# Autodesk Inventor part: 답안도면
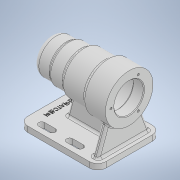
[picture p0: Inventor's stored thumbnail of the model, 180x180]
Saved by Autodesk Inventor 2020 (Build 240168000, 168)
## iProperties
Created: 2021-10
Part Number: 답안도면
Material: 일반
Document SubType Name: Modeling
Designer: user
Density: 1 g/cm^3
Appearance: 기본값
Author: user
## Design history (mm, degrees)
sketch "스케치1"
  geometry: L1 (0, 0)-(0, 34); L2 (0, 34)-(-32, 34); L3 (-32, 34)-(-32, 30); L4 (-32, 30)-(-66, 30); L5 (-66, 30)-(-66, 27); L6 (-66, 27)-(-88, 27); L7 (-88, 27)-(-88, 25); L8 (-88, 25)-(-112, 25); L9 (-112, 25)-(-112, 0); L10 (-112, 0)-(0, 0)
  constraints: 20 end point, 9 perpendicular, 1 vertical
  dimensions: "d0" = 24 distance of L7.end L8.end; "d1" = 46 distance between parallel lines of L5 L9; "d2" = 80 distance between parallel lines of L3 L9; "d3" = 112 distance between parallel lines of L1 L9; "d4" = 50 diameter of L8 L10; "d5" = 54 diameter of L6 L10; "d6" = 60 diameter of L4 L10; "d7" = 68 diameter of L2 L10
revolve "회전1" sketch "스케치1" stored, may be unused: angle "d8" = 90 deg
sketch "스케치2"
  geometry: C1 r 21 at (0, 0); 1 further point
  constraints: 1 centre point, 1 coincident
  dimensions: "d9" = 42 diameter of C1
extrude "돌출1" cut sketch "스케치2" distance "d10" = 15; taper "d11" = 0 deg
sketch "스케치3"
  geometry: C1 r 24 at (0, 0); 1 further point
  constraints: 1 centre point, 1 coincident
  dimensions: "d12" = 48 diameter of C1
extrude "돌출2" cut sketch "스케치3" distance "d13" = 54; taper "d14" = 0 deg
sketch "스케치4"
  geometry: C1 r 21 at (0, 0); 1 further point
  constraints: 1 centre point, 1 coincident
  dimensions: "d15" = 42 diameter of C1
extrude "돌출3" cut sketch "스케치4" distance "d16" = 12; taper "d17" = 0 deg
sketch "스케치5"
  geometry: C1 r 24 at (0, 0) reference; C2 r 17.5 at (0, 0); 1 further point
  constraints: 1 centre point, 1 coincident
  dimensions: "d18" = 35 diameter of C2
extrude "돌출4" cut sketch "스케치5" distance "d19" = 18; taper "d20" = 0 deg
sketch "스케치6"
  geometry: C1 r 16 at (0, 0); 1 further point
  constraints: 1 centre point, 1 coincident
  dimensions: "d21" = 32 diameter of C1
extrude "돌출5" cut sketch "스케치6" distance "d22" = 4; taper "d23" = 0 deg
sketch "스케치7"
  geometry: C1 r 21 at (0, 0) reference; C2 r 10.5 at (0, 0); 1 further point
  constraints: 1 centre point, 1 coincident
  dimensions: "d24" = 21 diameter of C2
extrude "돌출6" cut sketch "스케치7" distance "d25" = 3; taper "d26" = 0 deg
node "작업 평면1"
sketch "스케치10"
  geometry: L1 (112, 45)-(0, 45); L2 (0, 45)-(0, -45); L3 (0, -45)-(112, -45); L4 (112, -45)-(112, 45); L5 (112, 45)-(0, -45); L6 (0, 45)-(112, -45); L7 (112, 25)-(112, -25) reference; 3 further points
  constraints: 12 end point, 3 midpoint, 2 parallel, 1 horizontal, 1 horizontal alignment, 1 perpendicular, 1 point on line
  dimensions: "d28" = 112 distance of L3.end L2.end; "d29" = 90 distance of L2.end L1.end
extrude "돌출7" join sketch "스케치10" distance "d30" = 8; taper "d31" = 0 deg
sketch "스케치11"
  geometry: L1 (-85, -4)-(-8, -4); L2 (-8, -4)-(-8, 4); L3 (-8, 4)-(-85, 4); L4 (-85, 4)-(-85, -4); L5 (-85, -4)-(-8, 4); L6 (-8, -4)-(-85, 4); L7 (-112, -45)-(0, -45) reference; L8 (0, -45)-(0, 45) reference; 4 further points
  constraints: 12 end point, 4 midpoint, 2 parallel, 1 horizontal, 1 horizontal alignment, 1 perpendicular
  dimensions: "d34" = 8 distance between parallel lines of L8 L2; "d35" = 8 distance of L3.end L1.start; "d36" = 77 distance of L2.end L3.end
extrude "돌출8" join sketch "스케치11" stored distance "d37" = 8; taper "d38" = 0 deg
sketch "스케치12"
  geometry: L1 (-41, -8)-(-41, 0) reference; L2 (-41, 0)-(0, 0) reference; L3 (0, 0)-(0, 28.236) reference; L4 (8, 28.236)-(8, 0) reference; L5 (8, 0)-(49, 0) reference; L6 (49, 0)-(49, -8) reference; L7 (49, -8)-(-41, -8) reference; L8 (0, 0)-(8, 0) reference; L9 (-19.409, 37.342)-(-33, 0); L10 (49, 0)-(-41, 0) reference; C1 r 21 at (4, 62) reference; A1 r 34 centre (4, 62) between (8, 28.236) and (0, 28.236) reference; A2 r 34 centre (4, 62) between (0, 28.236) and (8, 28.236) reference; 2 further points
  constraints: 2 end point, 1 point on circle, 1 point on line
  dimensions: "d39" = 8 distance from line of L1 L9.end; "d40" = 110 deg angle of L2 L9
extrude "돌출9" join sketch "스케치12" distance "d41" = 8; taper "d42" = 0 deg
sketch "스케치14"
  geometry: L1 (-92, 33)-(-77, 33); L2 (-92, 28.5)-(-77, 28.5); L3 (-77, 37.5)-(-92, 37.5); L4 (-112, 45)-(-112, -45) reference; L5 (-52, 33)-(-37, 33); L6 (-52, 28.5)-(-37, 28.5); L7 (-37, 37.5)-(-52, 37.5); A1 r 4.5 centre (-92, 33) between (-92, 37.5) and (-92, 28.5); A2 r 4.5 centre (-77, 33) between (-77, 28.5) and (-77, 37.5); A3 r 4.5 centre (-52, 33) between (-52, 37.5) and (-52, 28.5); A4 r 4.5 centre (-37, 33) between (-37, 28.5) and (-37, 37.5); 3 further points
  constraints: 16 end point, 8 point on circle, 8 tangent, 4 centre point, 2 horizontal, 2 midpoint, 2 parallel
  dimensions: "d43" = 9 diameter of A2; "d44" = 20 distance from line of L1.start L4; "d45" = 15 distance of L1.end L1.start; "d46" = 9 diameter of A4; "d47" = 25 distance of L5.start L1.end; "d48" = 15 distance of L5.end L5.start; "d49" = 33 vertical distance of point (0, 0) point (-84.5, 33); "d50" = 33 vertical distance of point (0, 0) point (-44.5, 33)
extrude "돌출10" cut sketch "스케치14" distance "d51" = 30; taper "d52" = 0 deg
sketch "스케치16"
  geometry: C1 r 10.5 at (0, 0) reference; 2 further points
  constraints: 1 horizontal alignment
  dimensions: "d54" = 26 distance of point (0, 0) point (-26, 0)
hole "구멍1" sketch "스케치16" at (-26, 0) diameter "d55" = 3.242; stored, may be unused: countersink angle "d59" = 90 deg, drill point angle "d61" = 118 deg; dims "d56" = 8, "d57" = 4, "d58" = 2, "d60" = 11.8
chamfer "모따기1" distance "d65" = 1; stored, may be unused: second distance "d66" = 2, angle "d67" = 45 deg
fillet "모깎기1" dims "d68" = 3
fillet "모깎기2" dims "d69" = 0.3
fillet "모깎기3" dims "d70" = 3
fillet "모깎기4" dims "d71" = 8
fillet "모깎기5" dims "d72" = 3
feature "면 기울기1" dims angle "d73" = 15 deg
fillet "모깎기6" dims "d74" = 12
fillet "모깎기7" dims "d75" = 3
fillet "모깎기8" dims "d76" = 3
fillet "모깎기9" dims "d77" = 3
sketch "스케치17"
  geometry: L1 (-112, 33)-(-112, -33) reference; 2 further points
  constraints: 1 horizontal alignment, 1 other
  dimensions: "d78" = 12 distance from line of point (-100, 0) L1
feature "엠보싱1" sketch "스케치17" dims "d0" = 24, "d1" = 46, "d2" = 80, "d3" = 112, "d4" = 50, "d5" = 54, "d6" = 60, "d7" = 68, "d79" = 0.5, "d80" = 0
node "솔리드1"
mirror "미러1"
mirror "미러2"
pattern_circular "원형 패턴1" dims angle "d63" = 360 deg
node "절단 모서리 투영1"
feature "A9D066F2-1C7D-4E18-AEED-F7BC21143FA4" dims "d55" = 3.242, "d56" = 8, "d57" = 4, "d58" = 2, "d59" = 90 deg, "d60" = 11.8, "d61" = 118 deg
